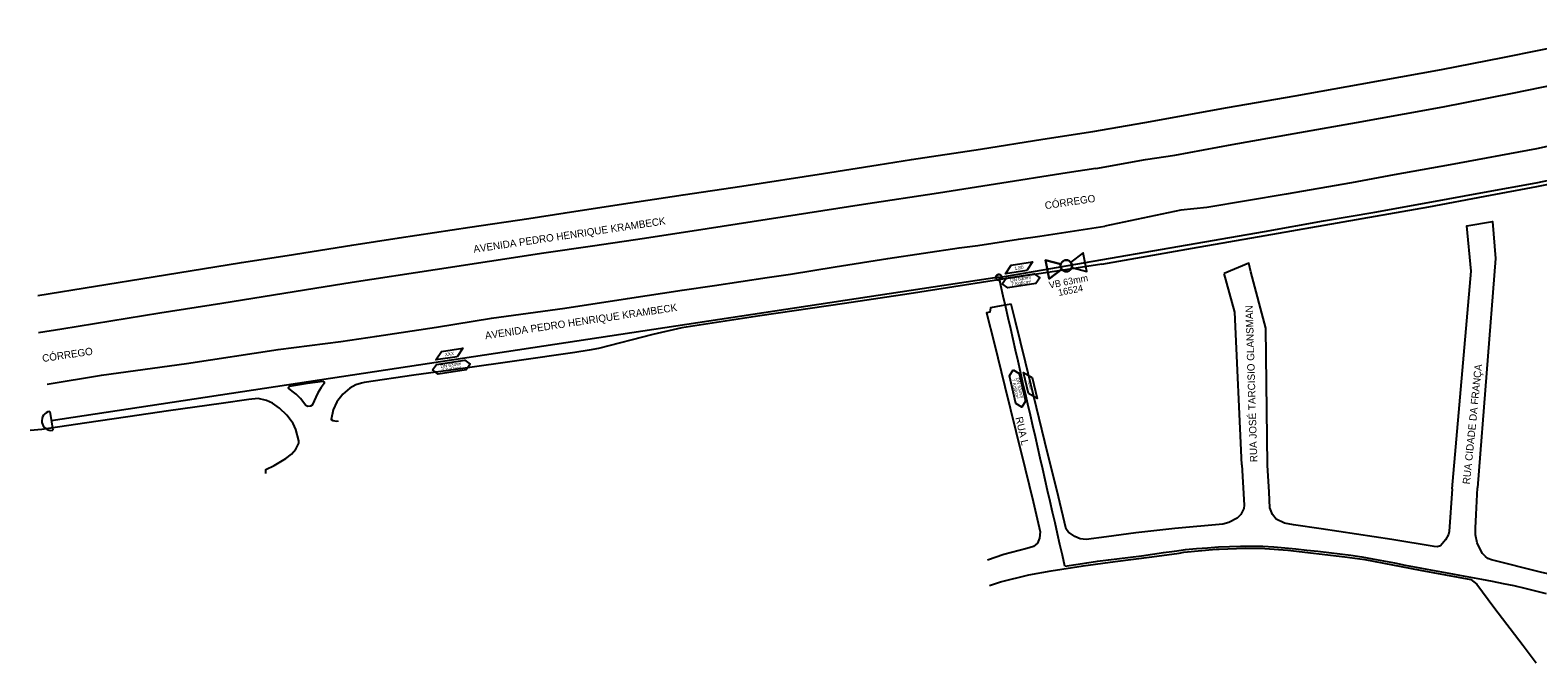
# Model space of a CAD drawing. Extents: x 656692 to 673945, y 7585994 to 7599066.
# Drawn here: x 656692 to 658033, y 7590478 to 7591041 of the extents above; entities that cross this region are included whole.
import ezdxf

# ---------------------------------------------------------------- set-up
doc = ezdxf.new("R2010")
doc.units = 0
for name, color, linetype in [('LOGRADOURO', 7, 'Continuous'), ('LOGRADOURO_TEXTO', 7, 'Continuous'), ('SIMBOLO', 7, 'Continuous'), ('TEXTO', 7, 'Continuous'), ('TUBO_PEAD_GN_63', 7, 'Continuous'), ('VALVULA_PEAD_63', 7, 'Continuous')]:
    doc.layers.add(name, color=color, linetype=linetype)

# ---------------------------------------------------------------- blocks, each defined once
blk = doc.blocks.new('VALVULA_PEAD_DN_9')
at = {"layer": 'VALVULA_PEAD_63'}
for points in [[(-1.14, 0.57), (-4.25, 2.13), (-4.25, -2.13), (-1.14, -0.57)], [(-1.14, -0.57), (-4.25, -2.13), (-4.25, 2.13), (-1.14, 0.57)], [(1.14, -0.57), (4.25, -2.13), (4.25, 2.13), (1.14, 0.57)], [(1.14, -0.57), (4.25, -2.13), (4.25, 2.13), (1.14, 0.57)]]:
    blk.add_lwpolyline(points, dxfattribs=at)
blk.add_circle((0, 0), 1.28, dxfattribs=at)
for start, end in [(90, 270), (153.4349, 206.5651), (270, 90), (0, 26.5651), (333.4349, 0)]:
    blk.add_arc((0, 0), 1.28, start, end, dxfattribs=at)
blk = doc.blocks.new('INTERLIGACAO_5')
at = {"layer": 'SIMBOLO'}
blk.add_circle((0, 0), 1.28, dxfattribs=at)
for start, end in [(0, 180), (180, 0)]:
    blk.add_arc((0, 0), 1.28, start, end, dxfattribs=at)

msp = doc.modelspace()

# ---------------------------------------------------------------- linework, layer by layer
at = {"layer": 'LOGRADOURO'}
for points in [[(658426.3, 7591040.9), (658374.2, 7591023.1), (658313.8, 7591004), (658272.6, 7590992.7), (658221.4, 7590978.9), (658166.9, 7590965.6), (658110.5, 7590952.5), (658032.1, 7590935.5), (657955.3, 7590921.3), (657905.4, 7590912.2), (657867.4, 7590905.3), (657809.5, 7590895.2), (657738.9, 7590883.3), (657715.8, 7590880.8), (657648, 7590866.7)], [(657637.4, 7590950.9), (657683.6, 7590958.9), (657757.3, 7590972.2), (657817.5, 7590982.5), (657875.3, 7590993), (657947.4, 7591006), (658002.1, 7591016.6), (658066.7, 7591029.8)], [(657710.3, 7590929.9), (657761.5, 7590939.2), (657816.5, 7590949.2), (657871.8, 7590958.9), (657914.6, 7590966.6), (657949.1, 7590972.9), (658010.7, 7590984.8), (658088.9, 7591001)], [(656699.2, 7590805.1), (656801.8, 7590821.5), (656880.3, 7590834.3), (656920.8, 7590840.6), (656978.4, 7590849.9), (657020.6, 7590856.3), (657083.3, 7590865.7), (657135.7, 7590873.6), (657168.2, 7590878.6), (657216.2, 7590885.8), (657273.2, 7590894.5), (657325.3, 7590902.3), (657397.9, 7590913.5), (657446.5, 7590921.1), (657476.2, 7590925.8), (657537.6, 7590935.2), (657593.1, 7590943.9), (657637.4, 7590950.9)], [(657640.1, 7590918), (657684.4, 7590925.8), (657710.3, 7590929.9)], [(657640.1, 7590918), (657614.7, 7590914.1), (657550.9, 7590903.9), (657500.3, 7590896.1), (657433.4, 7590885.8), (657361.1, 7590874.6), (657294.5, 7590864.3), (657238.7, 7590855.8), (657192.5, 7590848.9), (657149.2, 7590842.6), (657052.5, 7590827.9), (656978.7, 7590816.7), (656945.4, 7590811.3), (656862.7, 7590797.9), (656807.6, 7590789.2), (656720.6, 7590775.2), (656699.8, 7590771.9)], [(657645.4, 7590833), (657726.2, 7590847.2), (657790.7, 7590858.4), (657843.2, 7590867.7), (657888.9, 7590875.5), (657936.2, 7590884), (657986.5, 7590893.4), (658032.4, 7590901.8), (658086.5, 7590912.9)], [(656707.3, 7590726.2), (656755.7, 7590734.1), (656831.2, 7590744.6), (656912.8, 7590757.1), (656968.7, 7590764), (657000.5, 7590768.9), (657053.7, 7590776.9), (657102.6, 7590784.9), (657167.7, 7590793.7), (657223.6, 7590802.4), (657272.3, 7590809.7), (657300.8, 7590813.9), (657347.8, 7590820.9), (657368.4, 7590824.1), (657408.4, 7590830.5), (657455, 7590838), (657518.6, 7590847.5), (657535.3, 7590849.5), (657571.3, 7590855), (657590.2, 7590857.8), (657648, 7590866.7)], [(657957, 7590633.2), (657973.9, 7590826.6), (657970.2, 7590867.1), (657992.8, 7590870.8), (657995.7, 7590837.8), (657979.6, 7590634.1)], [(657645.4, 7590833), (657605.5, 7590826.7), (657579.2, 7590822.8), (657553.6, 7590819), (657523.2, 7590814.1), (657474.2, 7590806.5), (657416.6, 7590798), (657341.3, 7590786.8), (657272, 7590776.2), (657246.2, 7590770.2), (657197.8, 7590757.9), (657189.5, 7590756.3), (657176.8, 7590754.4), (657125.1, 7590747), (657077, 7590740.2), (657033.5, 7590734.2), (656989.5, 7590727.6), (656986.9, 7590727.1), (656981.8, 7590725.6), (656976.5, 7590722.6), (656970.3, 7590717.4), (656965.1, 7590710.4), (656961.9, 7590703.4), (656959.9, 7590694.7), (656961.6, 7590693.8), (656965.1, 7590693.4), (656966.5, 7590693.7)], [(657792.7, 7590654.2), (657791.4, 7590776.1), (657778.1, 7590826.2), (657776.2, 7590833.9), (657754.3, 7590824.5)], [(657770, 7590654.6), (657763.8, 7590790.2), (657754.3, 7590824.5)], [(657564.9, 7590797.3), (657555.9, 7590795.9), (657546.3, 7590794), (657545.9, 7590790.3), (657542.9, 7590789.6), (657549.6, 7590763), (657559.3, 7590724.2), (657569, 7590684.5), (657577.4, 7590650.8), (657584.4, 7590621.8), (657590.7, 7590595), (657590.1, 7590589.4), (657588.2, 7590584.7), (657584.6, 7590581.9), (657578.6, 7590580), (657558.2, 7590574.6), (657543.8, 7590569.8)], [(657613.8, 7590597.4), (657605.3, 7590632.3), (657597.1, 7590665.2), (657577.6, 7590745.6), (657568.8, 7590782), (657564.9, 7590797.3)], [(656952.7, 7590728.9), (656953.8, 7590728.2), (656953.9, 7590726.8), (656951, 7590723.1), (656948.1, 7590718.4), (656943, 7590707.6), (656941.5, 7590706.5), (656939.2, 7590706.3), (656937.6, 7590707.3), (656932.7, 7590713.4), (656928.9, 7590717.2), (656925.2, 7590720.1), (656922.1, 7590722.5), (656922, 7590723.2), (656922.9, 7590724.5), (656939, 7590727), (656952.7, 7590728.9)], [(656902, 7590646.9), (656901.8, 7590650.4), (656909.4, 7590654), (656919.8, 7590660), (656924.7, 7590663.8), (656928.6, 7590668.3), (656931.2, 7590673.7), (656931.2, 7590675.9), (656928.5, 7590685.9), (656926.1, 7590691.3), (656920.7, 7590698.6), (656914, 7590704.8), (656907.7, 7590709.3), (656902.6, 7590711.7), (656895.2, 7590713.3), (656886.8, 7590712.7), (656862.1, 7590709.1), (656815.3, 7590702.4), (656779.1, 7590697.1), (656740.5, 7590691.5), (656702.8, 7590686), (656692.3, 7590685)], [(657770, 7590654.6), (657772, 7590618.7), (657771.6, 7590615.5), (657769.2, 7590610.2), (657765.7, 7590607.1), (657758.5, 7590603.3), (657753.1, 7590601.8), (657710.4, 7590598), (657675.6, 7590594.1), (657649.7, 7590590.5), (657631.5, 7590588.1), (657626.2, 7590588.7), (657621.3, 7590590.6), (657615.9, 7590594.7), (657613.8, 7590597.4)], [(657957, 7590633.2), (657954.5, 7590595.1), (657953.9, 7590592.6), (657951, 7590587.8), (657946.6, 7590582.5), (657943.8, 7590581.7), (657941.1, 7590581.8), (657903.3, 7590588.1), (657840.4, 7590597.6), (657815.8, 7590601.1), (657807.9, 7590602.6), (657800.6, 7590606.3), (657797.2, 7590610.4), (657795, 7590616.1), (657794.2, 7590630.2), (657792.7, 7590654.2)], [(658056.6, 7590560.3), (658053.7, 7590555.5), (658050, 7590555.7), (658035.5, 7590559), (657991.9, 7590569.9), (657988.8, 7590571.2), (657986.6, 7590572.9), (657984, 7590575.6), (657981.8, 7590579.5), (657979.3, 7590585.1), (657977.8, 7590592.2), (657977.8, 7590598.3), (657978.5, 7590610.4), (657979.6, 7590634.1)], [(657545.4, 7590547.2), (657555.3, 7590550.3), (657580.5, 7590556.6), (657600.4, 7590560.3), (657628.7, 7590564.7), (657657.2, 7590568.6), (657689.9, 7590572.7), (657714.1, 7590576), (657718.3, 7590576.8), (657747.2, 7590579.4), (657749.7, 7590579.6), (657772.8, 7590580.3), (657790.3, 7590580), (657811, 7590578.7), (657861.7, 7590572.8), (657879.4, 7590570.3), (657928.5, 7590560.9), (657973.5, 7590552.5), (657979.1, 7590548.5), (657994.2, 7590528), (658020.2, 7590493.7), (658031.6, 7590478.4)]]:
    msp.add_lwpolyline(points, dxfattribs=at)
at = {"layer": 'SIMBOLO'}
for points in [[(657578.8, 7590827.3), (657559.8, 7590824.4), (657564.8, 7590832), (657583.8, 7590834.9)], [(657072.2, 7590750.6), (657053.2, 7590747.7), (657058.1, 7590755.3), (657077.1, 7590758.2)], [(657580.1, 7590717.8), (657575.7, 7590736.5), (657583.6, 7590732.2), (657588, 7590713.5)]]:
    msp.add_lwpolyline(points, close=True, dxfattribs=at)
for points in [[(657556.8, 7590815.5), (657560.4, 7590820.5), (657585.4, 7590824.3), (657590.4, 7590820.6), (657586.7, 7590815.6), (657561.7, 7590811.8), (657556.8, 7590815.5)], [(657050.1, 7590738.8), (657053.8, 7590743.8), (657078.8, 7590747.6), (657083.7, 7590743.9), (657080.1, 7590738.9), (657055.1, 7590735.1), (657050.1, 7590738.8)], [(657566.5, 7590738.9), (657571.8, 7590735.6), (657577.6, 7590711), (657574.3, 7590705.8), (657569, 7590709), (657563.3, 7590733.6), (657566.5, 7590738.9)]]:
    msp.add_lwpolyline(points, dxfattribs=at)
at = {"layer": 'TUBO_PEAD_GN_63'}
for p, q in [((657554, 7590821.2), (656711.1, 7590693.6)), ((656709.8, 7590702), (656712.5, 7590685.2))]:
    msp.add_line(p, q, dxfattribs=at)
for points in [[(657553.9, 7590821), (657790, 7590862), (657842.6, 7590871.3), (657888.2, 7590879.1), (657935.6, 7590887.6), (657985.8, 7590897), (658031.7, 7590905.3), (658085.7, 7590916.5)], [(657612.6, 7590564.4), (657610.4, 7590574), (657608.2, 7590583.6), (657606, 7590593.2), (657603.8, 7590602.8), (657601.6, 7590612.3), (657599.4, 7590621.9), (657597.2, 7590631.5), (657595, 7590641.1), (657592.9, 7590650.7), (657590.7, 7590660.3), (657588.5, 7590669.9), (657586.3, 7590679.5), (657584.1, 7590689.1), (657581.9, 7590698.7), (657579.7, 7590708.3), (657577.5, 7590717.9), (657575.3, 7590727.5), (657573.2, 7590737.1), (657571, 7590746.7), (657568.8, 7590756.3), (657566.6, 7590765.9), (657564.4, 7590775.5), (657562.2, 7590785.1), (657560, 7590794.7), (657557.8, 7590804.3), (657555.6, 7590813.9), (657554, 7590821.2)], [(657612.6, 7590564.4), (657622.3, 7590565.9), (657632, 7590567.4), (657641.7, 7590568.8), (657651.5, 7590570.1), (657661.3, 7590571.3), (657671, 7590572.5), (657680.8, 7590573.7), (657690.6, 7590574.9), (657700.3, 7590576.4), (657710, 7590577.8), (657719.8, 7590579.1), (657729.6, 7590580), (657739.4, 7590580.8), (657749.2, 7590581.6), (657759.1, 7590581.9), (657768.9, 7590582.2), (657778.7, 7590582.2), (657788.6, 7590582), (657798.4, 7590581.5), (657808.2, 7590580.8), (657818, 7590579.8), (657827.8, 7590578.7), (657837.6, 7590577.6), (657847.3, 7590576.4), (657857.1, 7590575.3), (657866.9, 7590574.2), (657876.6, 7590572.8), (657886.3, 7590571), (657896, 7590569.1), (657905.6, 7590567.3), (657915.3, 7590565.4), (657925, 7590563.6), (657934.6, 7590561.7), (657944.3, 7590559.9), (657954, 7590558.1), (657963.7, 7590556.3), (657973.3, 7590554.5), (657983, 7590552.7), (657992.7, 7590550.9), (658002.4, 7590549.1), (658012, 7590547.2), (658021.6, 7590544.8), (658031.1, 7590542.4), (658040.7, 7590540)]]:
    msp.add_lwpolyline(points, dxfattribs=at)
msp.add_arc((656711.1, 7590693.6), 8.51, 99.2356, 279.2356, dxfattribs=at)

# ---------------------------------------------------------------- block references
at = {"layer": 'SIMBOLO', "xscale": 1.9999999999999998, "yscale": 1.9999999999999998, "rotation": 59.917362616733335}
msp.add_blockref('INTERLIGACAO_5', (657553.8, 7590821.2), dxfattribs=at)
at = {"layer": 'VALVULA_PEAD_63', "xscale": 3.9999999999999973, "yscale": 3.9999999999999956, "rotation": 11.048006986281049}
msp.add_blockref('VALVULA_PEAD_DN_9', (657613.8, 7590831.4), dxfattribs=at)

# ---------------------------------------------------------------- texts
for s, p in [('VB 63mm', (657599, 7590811.2)), ('16524', (657607.2, 7590804.6))]:
    msp.add_text(s, height=6, rotation=11.048).set_placement(p)
at = {"layer": 'LOGRADOURO_TEXTO'}
for s, height, rotation, p in [('CÓRREGO', 6.56, 8.4265, (657595.2, 7590881.7)), ('AVENIDA PEDRO HENRIQUE KRAMBECK', 6.562, 8.4265, (657087, 7590843)), ('AVENIDA PEDRO HENRIQUE KRAMBECK', 6.562, 8.4265, (657097.3, 7590766.1)), ('RUA JOSÉ TARCISIO GLANSMAN', 6.562, 91.699, (657783.8, 7590656.9)), ('CÓRREGO', 6.56, 8.4265, (656703.5, 7590745.8)), ('RUA CIDADE DA FRANÇA', 6.562, 84.1908, (657972.8, 7590636.9)), ('RUA L', 6.56, 282.8506, (657568.5, 7590696.4))]:
    msp.add_text(s, height=height, rotation=rotation, dxfattribs=at).set_placement(p)
at = {"layer": 'TEXTO'}
for s, rotation, p in [('1,80', 8.6249, (657568, 7590827.6)), ('DN 63mm', 8.6249, (657564.2, 7590817.1)), ('7 Kgf/cm²', 8.6249, (657565.2, 7590813.4)), ('DN 63mm', 8.6249, (657057.5, 7590740.4)), ('XXX', 8.6249, (657061.3, 7590750.9)), ('7 Kgf/cm²', 8.6249, (657058.6, 7590736.7)), ('DN 63mm', 283.1816, (657568.8, 7590731.6)), ('7 Kgf/cm²', 283.1816, (657565.2, 7590730.3)), ('XXX', 283.1816, (657579.4, 7590728.7))]:
    msp.add_text(s, height=3, rotation=rotation, dxfattribs=at).set_placement(p)

doc.saveas('drawing.dxf')
